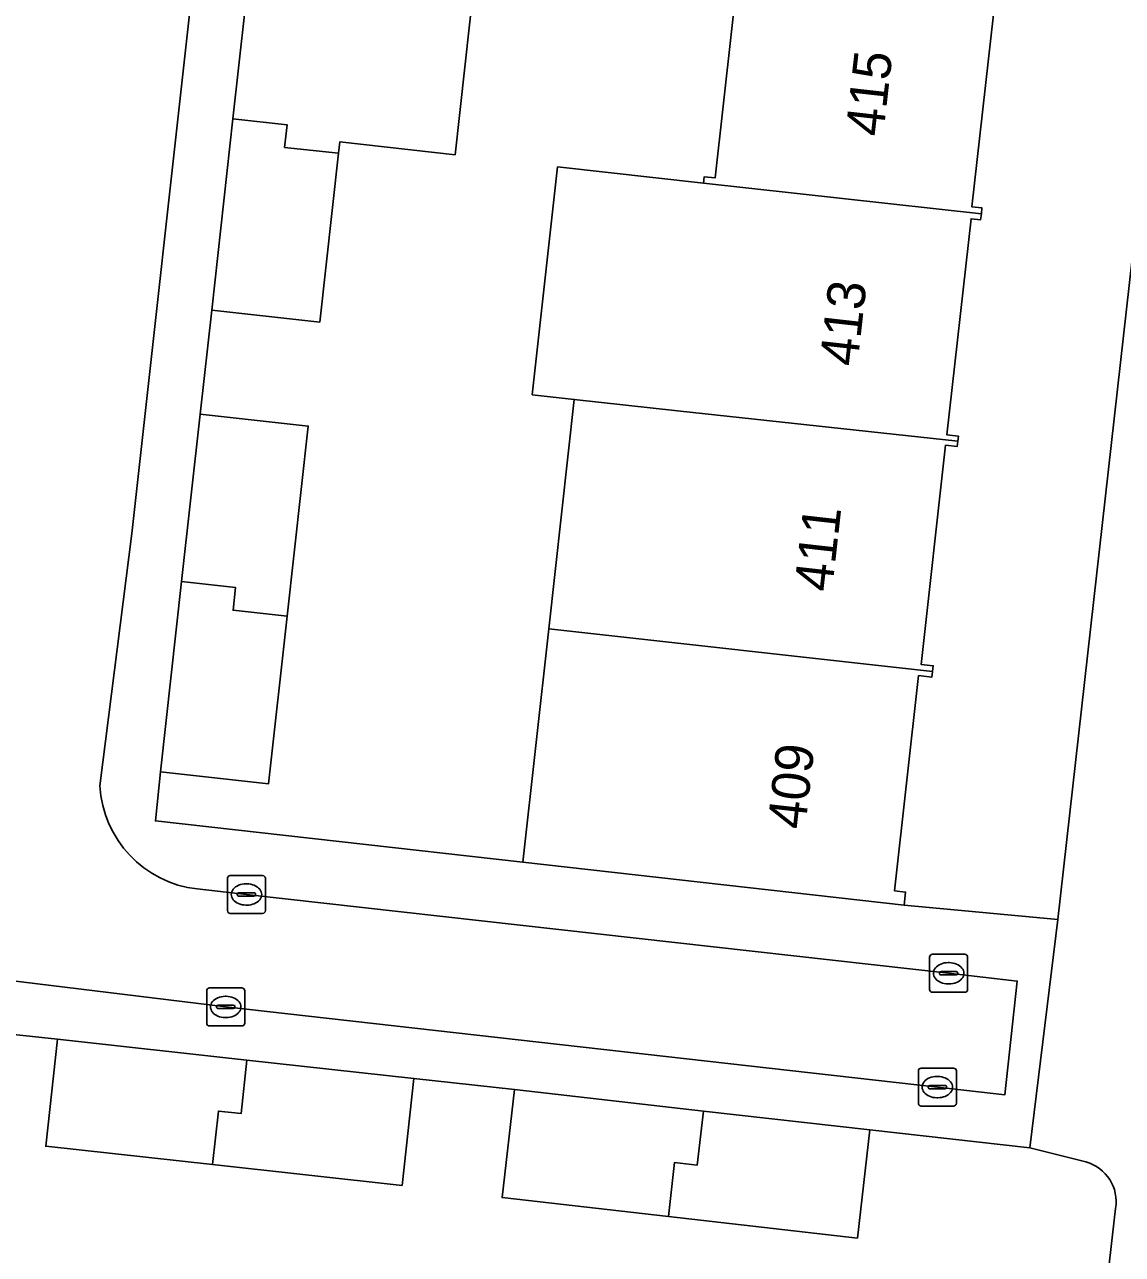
# Model space of a CAD drawing. Extents: x 161928 to 163071, y 386474 to 387428.
# Drawn here: x 162046.14 to 162075.08, y 386860.59 to 386892.98 of the extents above; entities that cross this region are included whole.
import ezdxf

# ---------------------------------------------------------------- set-up
doc = ezdxf.new("R2010")
doc.units = 0
for name, color, linetype in [('IMGEO_Erf', 7, 'Continuous'), ('IMGEO_Kolk', 7, 'Continuous'), ('IMGEO_Pand', 7, 'Continuous'), ('IMGEO_Pand_nummerreeks', 7, 'Continuous'), ('IMGEO_Rijbaan_lokaal_open', 7, 'Continuous'), ('IMGEO_Voetpad_open', 7, 'Continuous')]:
    doc.layers.add(name, color=color, linetype=linetype)

msp = doc.modelspace()

# ---------------------------------------------------------------- linework, layer by layer
at = {"layer": 'IMGEO_Erf'}
for points in [[(162071.746, 386893.879), (162071.107, 386888.184), (162071.376, 386888.154), (162071.359, 386887.998), (162071.341, 386887.841), (162071.087, 386887.87), (162070.449, 386882.18), (162070.753, 386882.146), (162070.738, 386882.008), (162070.722, 386881.87), (162070.418, 386881.904), (162069.77, 386876.13), (162070.09, 386876.094), (162070.073, 386875.945), (162070.056, 386875.796), (162069.707, 386875.835), (162069.071, 386870.166), (162069.363, 386870.134), (162069.325, 386869.792), (162073.376, 386869.412), (162077.454, 386905.628)], [(162058.005, 386894.177), (162057.49, 386889.553), (162054.45, 386889.891), (162054.417, 386889.592), (162053.922, 386885.147), (162051.074, 386885.464), (162050.772, 386882.725), (162053.621, 386882.408), (162053.064, 386877.397), (162052.573, 386872.984), (162049.724, 386873.301), (162049.592, 386872.006), (162059.278, 386870.918), (162059.96, 386877.064), (162060.631, 386883.11), (162059.525, 386883.232), (162060.19, 386889.235), (162064.036, 386888.809), (162064.055, 386888.976), (162064.341, 386888.944), (162064.995, 386894.775)], [(162074.116, 386863.024), (162072.637, 386863.4), (162068.418, 386863.866), (162068.094, 386861.02), (162063.113, 386861.587), (162058.73, 386862.086), (162059.054, 386864.932), (162056.402, 386865.226), (162056.092, 386862.406), (162051.096, 386862.955), (162046.702, 386863.437), (162047.012, 386866.257), (162044.442, 386866.531), (162044.134, 386863.731), (162039.159, 386864.277), (162034.781, 386864.758), (162035.089, 386867.558), (162033.572, 386867.709), (162033.74, 386869.218), (162032.12, 386869.403), (162029.159, 386843.54), (162030.856, 386843.347), (162071.281, 386838.739)], [(162072.375, 386839.683), (162074.895, 386861.796)]]:
    msp.add_lwpolyline(points, dxfattribs=at)
msp.add_arc((162073.828, 386861.98), 1.083, 350.2201, 74.5592, dxfattribs=at)
at = {"layer": 'IMGEO_Kolk'}
for p, q in [((162051.49, 386869.643), (162051.49, 386870.495)), ((162051.565, 386870.569), (162052.417, 386870.569)), ((162052.491, 386870.495), (162052.491, 386869.643)), ((162051.978, 386870.349), (162052.003, 386870.349)), ((162051.749, 386870.063), (162051.749, 386870.075)), ((162052.187, 386870.026), (162051.789, 386870.026)), ((162051.792, 386870.112), (162052.19, 386870.112)), ((162052.233, 386870.075), (162052.233, 386870.063)), ((162052.417, 386869.569), (162051.565, 386869.569)), ((162052.001, 386869.789), (162051.976, 386869.789)), ((162069.996, 386867.568), (162069.996, 386868.42)), ((162070.071, 386868.494), (162070.923, 386868.494)), ((162070.484, 386868.274), (162070.509, 386868.274)), ((162070.997, 386868.42), (162070.997, 386867.568)), ((162070.255, 386867.988), (162070.255, 386868)), ((162070.693, 386867.951), (162070.295, 386867.951)), ((162070.298, 386868.037), (162070.696, 386868.037)), ((162070.739, 386868), (162070.739, 386867.988)), ((162051.019, 386867.607), (162051.871, 386867.607)), ((162070.507, 386867.714), (162070.482, 386867.714)), ((162050.944, 386866.681), (162050.944, 386867.533)), ((162051.432, 386867.387), (162051.457, 386867.387)), ((162051.945, 386867.533), (162051.945, 386866.681)), ((162070.923, 386867.494), (162070.071, 386867.494)), ((162051.203, 386867.101), (162051.203, 386867.113)), ((162051.641, 386867.064), (162051.243, 386867.064)), ((162051.246, 386867.15), (162051.644, 386867.15)), ((162051.687, 386867.113), (162051.687, 386867.101)), ((162051.871, 386866.607), (162051.019, 386866.607)), ((162051.455, 386866.827), (162051.43, 386866.827)), ((162069.7, 386864.569), (162069.7, 386865.421)), ((162069.775, 386865.495), (162070.627, 386865.495)), ((162070.701, 386865.421), (162070.701, 386864.569)), ((162069.959, 386864.989), (162069.959, 386865.001)), ((162070.002, 386865.038), (162070.4, 386865.038)), ((162070.188, 386865.275), (162070.213, 386865.275)), ((162070.443, 386865.001), (162070.443, 386864.989)), ((162070.397, 386864.952), (162069.999, 386864.952)), ((162070.211, 386864.715), (162070.186, 386864.715)), ((162070.627, 386864.495), (162069.775, 386864.495))]:
    msp.add_line(p, q, dxfattribs=at)
for points in [[(162051.49, 386869.643), (162051.49, 386870.495)], [(162051.565, 386870.569), (162052.417, 386870.569)], [(162052.491, 386870.495), (162052.491, 386869.643)], [(162052.417, 386869.569), (162051.565, 386869.569)], [(162069.996, 386867.568), (162069.996, 386868.42)], [(162070.071, 386868.494), (162070.923, 386868.494)], [(162070.997, 386868.42), (162070.997, 386867.568)], [(162051.019, 386867.607), (162051.871, 386867.607)], [(162050.944, 386866.681), (162050.944, 386867.533)], [(162051.945, 386867.533), (162051.945, 386866.681)], [(162070.923, 386867.494), (162070.071, 386867.494)], [(162051.871, 386866.607), (162051.019, 386866.607)], [(162069.7, 386864.569), (162069.7, 386865.421)], [(162069.775, 386865.495), (162070.627, 386865.495)], [(162070.701, 386865.421), (162070.701, 386864.569)], [(162070.627, 386864.495), (162069.775, 386864.495)]]:
    msp.add_lwpolyline(points, dxfattribs=at)
for centre, radius, start, end in [((162051.567, 386870.493), 0.0765, 91.552, 178.448), ((162051.567, 386870.493), 0.0765, 91.552, 178.448), ((162052.415, 386870.493), 0.0765, 1.552, 88.448), ((162052.415, 386870.493), 0.0765, 1.552, 88.448), ((162051.789, 386870.072), 0.0403, 85.8775, 175.7526), ((162051.786, 386870.062), 0.0366, 178.938, 274.7102), ((162052.19, 386870.069), 0.043, 264.8664, 352.4533), ((162052.194, 386870.074), 0.0386, 1.7309, 96.639), ((162051.567, 386869.645), 0.0765, 181.552, 268.448), ((162051.567, 386869.645), 0.0765, 181.552, 268.448), ((162052.415, 386869.645), 0.0765, 271.552, 358.448), ((162052.415, 386869.645), 0.0765, 271.552, 358.448), ((162070.073, 386868.418), 0.0765, 91.552, 178.448), ((162070.073, 386868.418), 0.0765, 91.552, 178.448), ((162070.921, 386868.418), 0.0765, 1.552, 88.448), ((162070.921, 386868.418), 0.0765, 1.552, 88.448), ((162070.295, 386867.997), 0.0403, 85.8775, 175.7526), ((162070.292, 386867.987), 0.0366, 178.938, 274.7102), ((162070.696, 386867.994), 0.043, 264.8664, 352.4533), ((162070.7, 386867.999), 0.0386, 1.7309, 96.639), ((162051.021, 386867.531), 0.0765, 91.552, 178.448), ((162051.021, 386867.531), 0.0765, 91.552, 178.448), ((162051.869, 386867.531), 0.0765, 1.552, 88.448), ((162051.869, 386867.531), 0.0765, 1.552, 88.448), ((162070.073, 386867.57), 0.0765, 181.552, 268.448), ((162070.073, 386867.57), 0.0765, 181.552, 268.448), ((162070.921, 386867.57), 0.0765, 271.552, 358.448), ((162070.921, 386867.57), 0.0765, 271.552, 358.448), ((162051.243, 386867.11), 0.0403, 85.8775, 175.7526), ((162051.24, 386867.1), 0.0366, 178.938, 274.7102), ((162051.644, 386867.107), 0.043, 264.8664, 352.4533), ((162051.648, 386867.112), 0.0386, 1.7309, 96.639), ((162051.021, 386866.683), 0.0765, 181.552, 268.448), ((162051.021, 386866.683), 0.0765, 181.552, 268.448), ((162051.869, 386866.683), 0.0765, 271.552, 358.448), ((162051.869, 386866.683), 0.0765, 271.552, 358.448), ((162069.777, 386865.419), 0.0765, 91.552, 178.448), ((162069.777, 386865.419), 0.0765, 91.552, 178.448), ((162070.625, 386865.419), 0.0765, 1.552, 88.448), ((162070.625, 386865.419), 0.0765, 1.552, 88.448), ((162069.999, 386864.998), 0.0403, 85.8775, 175.7526), ((162069.996, 386864.988), 0.0366, 178.938, 274.7102), ((162070.4, 386864.995), 0.043, 264.8664, 352.4533), ((162070.404, 386865), 0.0386, 1.7309, 96.639), ((162069.777, 386864.571), 0.0765, 181.552, 268.448), ((162069.777, 386864.571), 0.0765, 181.552, 268.448), ((162070.625, 386864.571), 0.0765, 271.552, 358.448), ((162070.625, 386864.571), 0.0765, 271.552, 358.448)]:
    msp.add_arc(centre, radius, start, end, dxfattribs=at)
for centre, major_axis, ratio, start_param, end_param in [((162051.977, 386870.069), (-0.387, 0.002), 0.722429, 4.712389, 7.853982), ((162052.002, 386870.069), (-0.39, 0.002), 0.717154, 1.570796, 4.712389), ((162070.483, 386867.994), (-0.387, 0.002), 0.722429, 4.712389, 7.853982), ((162070.508, 386867.994), (-0.39, 0.002), 0.717154, 1.570796, 4.712389), ((162051.431, 386867.107), (-0.387, 0.002), 0.722429, 4.712389, 7.853982), ((162051.456, 386867.107), (-0.39, 0.002), 0.717154, 1.570796, 4.712389), ((162070.187, 386864.995), (-0.387, 0.002), 0.722429, 4.712389, 7.853982), ((162070.212, 386864.995), (-0.39, 0.002), 0.717154, 1.570796, 4.712389)]:
    msp.add_ellipse(centre, major_axis=major_axis, ratio=ratio, start_param=start_param, end_param=end_param, dxfattribs=at)
at = {"layer": 'IMGEO_Pand'}
for points in [[(162051.634, 386890.502), (162053.061, 386890.345), (162052.994, 386889.749), (162054.417, 386889.592), (162054.45, 386889.891), (162057.49, 386889.553), (162058.005, 386894.177), (162052.116, 386894.832)], [(162071.746, 386893.879), (162072.024, 386893.848), (162072.041, 386893.995), (162064.995, 386894.775), (162064.341, 386888.944), (162064.055, 386888.976), (162064.036, 386888.809), (162071.359, 386887.998), (162071.376, 386888.154), (162071.107, 386888.184)], [(162051.074, 386885.464), (162053.922, 386885.147), (162054.417, 386889.592), (162052.994, 386889.749), (162053.061, 386890.345), (162051.634, 386890.502)], [(162071.087, 386887.87), (162071.341, 386887.841), (162071.359, 386887.998), (162064.036, 386888.809), (162060.19, 386889.235), (162059.525, 386883.232), (162060.631, 386883.11), (162063.351, 386882.812), (162070.738, 386882.008), (162070.753, 386882.146), (162070.449, 386882.18)], [(162070.073, 386875.945), (162070.09, 386876.094), (162069.77, 386876.13), (162070.418, 386881.904), (162070.722, 386881.87), (162070.738, 386882.008), (162063.351, 386882.812), (162060.631, 386883.11), (162059.96, 386877.064)], [(162050.281, 386878.31), (162051.705, 386878.152), (162051.639, 386877.555), (162053.064, 386877.397), (162053.621, 386882.408), (162050.772, 386882.725)], [(162049.724, 386873.301), (162052.573, 386872.984), (162053.064, 386877.397), (162051.639, 386877.555), (162051.705, 386878.152), (162050.281, 386878.31)], [(162069.325, 386869.792), (162069.363, 386870.134), (162069.071, 386870.166), (162069.707, 386875.835), (162070.056, 386875.796), (162070.073, 386875.945), (162059.96, 386877.064), (162059.278, 386870.918)], [(162052.002, 386865.709), (162047.012, 386866.257), (162046.702, 386863.437), (162051.096, 386862.955), (162051.251, 386864.363), (162051.848, 386864.297)], [(162051.848, 386864.297), (162051.251, 386864.363), (162051.096, 386862.955), (162056.092, 386862.406), (162056.402, 386865.226), (162052.002, 386865.709)], [(162064.034, 386864.365), (162059.054, 386864.932), (162058.73, 386862.086), (162063.113, 386861.587), (162063.275, 386863.01), (162063.872, 386862.942)], [(162063.872, 386862.942), (162063.275, 386863.01), (162063.113, 386861.587), (162068.094, 386861.02), (162068.418, 386863.866), (162064.034, 386864.365)]]:
    msp.add_lwpolyline(points, close=True, dxfattribs=at)
at = {"layer": 'IMGEO_Rijbaan_lokaal_open'}
for points in [[(162052.188, 386908.526), (162044.948, 386909.235), (162044.59, 386906.099), (162044.231, 386902.963), (162043.873, 386899.828), (162043.515, 386896.692), (162043.156, 386893.556), (162042.798, 386890.42), (162042.44, 386887.285), (162042.082, 386884.149), (162041.723, 386881.013), (162041.365, 386877.877), (162041.007, 386874.742), (162040.648, 386871.606), (162040.29, 386868.47), (162051.445, 386867.107), (162070.201, 386864.995), (162071.98, 386864.795), (162072.306, 386867.789), (162070.497, 386867.994), (162051.991, 386870.069), (162050.693, 386870.214)], [(162048.13, 386872.928), (162048.97, 386879.58), (162052.188, 386908.526)]]:
    msp.add_lwpolyline(points, dxfattribs=at)
msp.add_arc((162051.021, 386873.091), 2.896, 183.2266, 263.4953, dxfattribs=at)
at = {"layer": 'IMGEO_Voetpad_open'}
for points in [[(162082.324, 386929.045), (162079.716, 386906.933), (162077.454, 386905.628), (162073.376, 386869.412), (162072.637, 386863.4), (162074.116, 386863.024)], [(162044.948, 386909.235), (162052.188, 386908.526), (162048.97, 386879.58), (162048.13, 386872.928)], [(162059.278, 386870.918), (162049.592, 386872.006), (162049.724, 386873.301), (162050.281, 386878.31), (162050.772, 386882.725), (162051.074, 386885.464), (162051.634, 386890.502), (162052.116, 386894.832)], [(162050.693, 386870.214), (162051.991, 386870.069), (162070.497, 386867.994), (162072.306, 386867.789), (162071.98, 386864.795), (162070.201, 386864.995), (162051.445, 386867.107), (162040.29, 386868.47), (162033.74, 386869.218), (162033.572, 386867.709), (162035.089, 386867.558), (162040.064, 386867.012), (162044.442, 386866.531), (162047.012, 386866.257), (162052.002, 386865.709), (162056.402, 386865.226), (162059.054, 386864.932), (162064.034, 386864.365), (162068.418, 386863.866), (162072.637, 386863.4), (162073.376, 386869.412), (162069.325, 386869.792), (162059.278, 386870.918)], [(162074.895, 386861.796), (162072.375, 386839.683)]]:
    msp.add_lwpolyline(points, dxfattribs=at)
for centre, radius, start, end in [((162051.021, 386873.091), 2.896, 183.2266, 263.4953), ((162073.828, 386861.98), 1.083, 350.2201, 74.5592)]:
    msp.add_arc(centre, radius, start, end, dxfattribs=at)

# ---------------------------------------------------------------- texts
at = {"layer": 'IMGEO_Pand_nummerreeks'}
for s, rotation, p in [('415', 83.5774, (162068.769, 386890.011)), ('413', 83.5774, (162068.088, 386883.959)), ('411', 83.5778, (162067.419, 386878.019)), ('409', 83.5778, (162066.714, 386871.762))]:
    msp.add_text(s, height=1, rotation=rotation, dxfattribs=at).set_placement(p)

doc.saveas('drawing.dxf')
